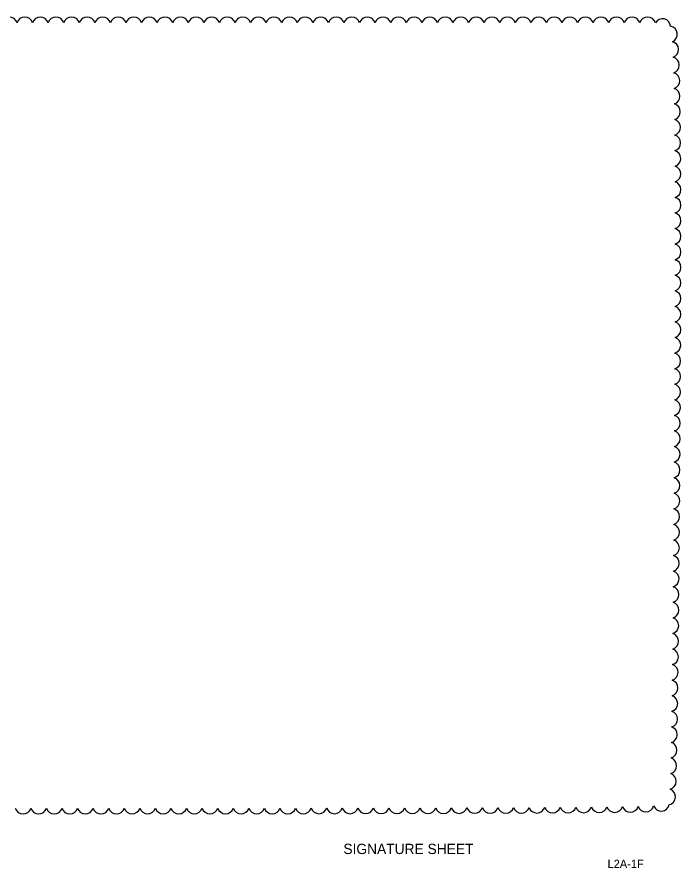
# Model space of a CAD drawing. Extents: x -811 to -790, y -2284 to -2178.
# Drawn here: x -803.16 to -795.1, y -2270.88 to -2260.55 of the extents above; entities that cross this region are included whole.
import ezdxf

# ---------------------------------------------------------------- set-up
doc = ezdxf.new("R2010")
doc.units = 0
for name, color, linetype in [('PlotBorder_dp', 7, 'Continuous'), ('ScratchEle_dp', 7, 'Continuous'), ('SheetLines_dp', 7, 'Continuous')]:
    doc.layers.add(name, color=color, linetype=linetype)

msp = doc.modelspace()

# ---------------------------------------------------------------- linework, layer by layer
at = {"layer": 'ScratchEle_dp'}
for centre, radius, start, end in [((-803.255, -2260.649), 0.0991, 17.5008, 162.5008), ((-803.066, -2260.649), 0.0991, 17.5, 162.5), ((-802.877, -2260.649), 0.0991, 17.5, 162.5), ((-802.688, -2260.649), 0.0991, 17.5, 162.5), ((-802.499, -2260.649), 0.0991, 17.5, 162.5), ((-802.31, -2260.649), 0.0991, 17.5, 162.5), ((-802.121, -2260.649), 0.0991, 17.5, 162.5), ((-801.932, -2260.649), 0.0991, 17.5, 162.5), ((-801.743, -2260.649), 0.0991, 17.5, 162.5), ((-801.554, -2260.649), 0.0991, 17.5, 162.5), ((-801.365, -2260.649), 0.0991, 17.5, 162.5), ((-801.176, -2260.649), 0.0991, 17.5, 162.5), ((-800.987, -2260.649), 0.0991, 17.5, 162.5), ((-800.798, -2260.649), 0.0991, 17.5, 162.5), ((-800.609, -2260.649), 0.0991, 17.5, 162.5), ((-800.42, -2260.649), 0.0991, 17.5, 162.5), ((-800.231, -2260.649), 0.0991, 17.5, 162.5), ((-800.042, -2260.649), 0.0991, 17.5, 162.5), ((-799.853, -2260.649), 0.0991, 17.5, 162.5), ((-799.664, -2260.649), 0.0991, 17.5, 162.5), ((-799.475, -2260.649), 0.0991, 17.5, 162.5), ((-799.286, -2260.649), 0.0991, 17.5, 162.5), ((-799.097, -2260.649), 0.0991, 17.5, 162.5), ((-798.908, -2260.649), 0.0991, 17.5, 162.5), ((-798.719, -2260.649), 0.0991, 17.5, 162.5), ((-798.53, -2260.649), 0.0991, 17.5, 162.5), ((-798.341, -2260.649), 0.0991, 17.5, 162.5), ((-798.152, -2260.649), 0.0991, 17.5, 162.5), ((-797.963, -2260.649), 0.0991, 17.5, 162.5), ((-797.774, -2260.649), 0.0991, 17.5, 162.5), ((-797.585, -2260.649), 0.0991, 17.5, 162.5), ((-797.396, -2260.649), 0.0991, 17.5, 162.5), ((-797.207, -2260.649), 0.0991, 17.5, 162.5), ((-797.018, -2260.649), 0.0991, 17.5, 162.5), ((-796.829, -2260.649), 0.0991, 17.5, 162.5), ((-796.64, -2260.649), 0.0991, 17.5, 162.5), ((-796.451, -2260.649), 0.0991, 17.5, 162.5), ((-796.262, -2260.649), 0.0991, 17.5, 162.5), ((-796.073, -2260.649), 0.0991, 17.5, 162.5), ((-795.884, -2260.649), 0.0991, 17.5, 162.5), ((-795.695, -2260.649), 0.0991, 17.5, 162.5), ((-795.506, -2260.649), 0.0991, 17.5, 162.5), ((-795.326, -2260.669), 0.099, 4.4162, 149.4162), ((-795.245, -2260.759), 0.0992, 294.7802, 79.7802), ((-795.229, -2260.945), 0.0991, 290.3649, 75.3649), ((-795.221, -2261.133), 0.0991, 289.3839, 74.3839), ((-795.215, -2261.322), 0.0991, 288.8712, 73.8712), ((-795.212, -2261.511), 0.0991, 288.5423, 73.5423), ((-795.208, -2261.7), 0.0991, 288.3081, 73.3081), ((-795.206, -2261.889), 0.0991, 288.1304, 73.1304), ((-795.204, -2262.078), 0.0991, 287.9896, 72.9896), ((-795.203, -2262.266), 0.0991, 287.8744, 72.8744), ((-795.202, -2262.455), 0.0991, 287.778, 72.778), ((-795.201, -2262.644), 0.0991, 287.6956, 72.6956), ((-795.2, -2262.833), 0.0991, 287.6243, 72.6243), ((-795.2, -2263.022), 0.0991, 287.5617, 72.5617), ((-795.2, -2263.211), 0.0991, 287.5062, 72.5062), ((-795.2, -2263.4), 0.0991, 287.4565, 72.4565), ((-795.2, -2263.589), 0.0991, 287.4117, 72.4117), ((-795.201, -2263.778), 0.0991, 287.3711, 72.3711), ((-795.201, -2263.967), 0.0991, 287.3339, 72.3339), ((-795.202, -2264.156), 0.0991, 287.2999, 72.2999), ((-795.202, -2264.345), 0.0991, 287.2684, 72.2684), ((-795.203, -2264.534), 0.0991, 287.2394, 72.2394), ((-795.204, -2264.723), 0.0991, 287.2123, 72.2123), ((-795.205, -2264.912), 0.0991, 287.1871, 72.1871), ((-795.206, -2265.101), 0.0991, 287.1635, 72.1635), ((-795.207, -2265.29), 0.0991, 287.1414, 72.1414), ((-795.209, -2265.479), 0.0991, 287.126, 72.126), ((-795.21, -2265.668), 0.0991, 287.1162, 72.1162), ((-795.211, -2265.857), 0.0991, 287.1058, 72.1058), ((-795.212, -2266.046), 0.0991, 287.0946, 72.0946), ((-795.214, -2266.235), 0.0991, 287.0827, 72.0827), ((-795.215, -2266.424), 0.0991, 287.0698, 72.0698), ((-795.217, -2266.613), 0.0991, 287.0559, 72.0559), ((-795.218, -2266.802), 0.0991, 287.0408, 72.0408), ((-795.22, -2266.991), 0.0991, 287.0244, 72.0244), ((-795.221, -2267.18), 0.0991, 287.0064, 72.0064), ((-795.223, -2267.369), 0.0991, 286.9865, 71.9865), ((-795.225, -2267.558), 0.0991, 286.9645, 71.9645), ((-795.226, -2267.747), 0.0991, 286.94, 71.94), ((-795.228, -2267.936), 0.0991, 286.9123, 71.9123), ((-795.23, -2268.125), 0.0991, 286.8807, 71.8807), ((-795.232, -2268.314), 0.0991, 286.8443, 71.8443), ((-795.235, -2268.503), 0.0991, 286.8016, 71.8016), ((-795.237, -2268.692), 0.0991, 286.7507, 71.7507), ((-795.24, -2268.881), 0.0991, 286.6884, 71.6884), ((-795.242, -2269.07), 0.0991, 286.6098, 71.6098), ((-795.246, -2269.259), 0.0991, 286.5063, 71.5063), ((-795.249, -2269.447), 0.0991, 286.3609, 71.3609), ((-795.253, -2269.636), 0.0991, 286.1344, 71.1344), ((-795.258, -2269.825), 0.0991, 285.7012, 70.7012), ((-795.268, -2270.013), 0.099, 283.7418, 68.7418), ((-803.087, -2270.122), 0.0991, 197.4952, 342.4952), ((-802.898, -2270.122), 0.0991, 197.5007, 342.5007), ((-802.709, -2270.122), 0.0991, 197.5043, 342.5043), ((-802.52, -2270.122), 0.0991, 197.5079, 342.5079), ((-802.331, -2270.122), 0.0991, 197.5117, 342.5117), ((-802.142, -2270.122), 0.0991, 197.5156, 342.5156), ((-801.953, -2270.122), 0.0991, 197.5197, 342.5197), ((-801.764, -2270.121), 0.0991, 197.5239, 342.5239), ((-801.575, -2270.121), 0.0991, 197.5284, 342.5284), ((-801.386, -2270.121), 0.0991, 197.533, 342.533), ((-801.197, -2270.121), 0.0991, 197.5379, 342.5379), ((-801.008, -2270.121), 0.0991, 197.543, 342.543), ((-800.819, -2270.121), 0.0991, 197.5483, 342.5483), ((-800.63, -2270.121), 0.0991, 197.554, 342.554), ((-800.441, -2270.121), 0.0991, 197.5599, 342.5599), ((-800.252, -2270.12), 0.0991, 197.5662, 342.5662), ((-800.063, -2270.12), 0.0991, 197.5729, 342.5729), ((-799.874, -2270.12), 0.0991, 197.5799, 342.5799), ((-799.685, -2270.12), 0.0991, 197.5874, 342.5874), ((-799.496, -2270.119), 0.0991, 197.5954, 342.5954), ((-799.307, -2270.119), 0.0991, 197.604, 342.604), ((-799.118, -2270.119), 0.0991, 197.6131, 342.6131), ((-798.929, -2270.118), 0.0991, 197.623, 342.623), ((-798.74, -2270.118), 0.0991, 197.6337, 342.6337), ((-798.551, -2270.117), 0.0991, 197.6452, 342.6452), ((-798.362, -2270.117), 0.0991, 197.6578, 342.6578), ((-798.173, -2270.116), 0.0991, 197.6716, 342.6716), ((-797.984, -2270.116), 0.0991, 197.6868, 342.6868), ((-797.795, -2270.115), 0.0991, 197.7037, 342.7037), ((-797.606, -2270.114), 0.0991, 197.7225, 342.7225), ((-797.417, -2270.114), 0.0991, 197.7438, 342.7438), ((-797.228, -2270.113), 0.0991, 197.768, 342.768), ((-797.039, -2270.112), 0.0991, 197.796, 342.796), ((-796.85, -2270.111), 0.0991, 197.8288, 342.8288), ((-796.661, -2270.11), 0.0991, 197.8681, 342.8681), ((-796.472, -2270.108), 0.0991, 197.9161, 342.9161), ((-796.283, -2270.107), 0.0991, 197.9767, 342.9767), ((-796.094, -2270.105), 0.0991, 198.0568, 343.0568), ((-795.905, -2270.103), 0.0991, 198.1697, 343.1697), ((-795.716, -2270.101), 0.0991, 198.3466, 343.3466), ((-795.528, -2270.097), 0.0991, 198.6898, 343.6898), ((-795.341, -2270.087), 0.0992, 202.4244, 347.4244)]:
    msp.add_arc(centre, radius, start, end, dxfattribs=at)

# ---------------------------------------------------------------- texts
at = {"layer": 'PlotBorder_dp'}
msp.add_text('       SIGNATURE SHEET         ', height=0.125, dxfattribs=at).set_placement((-799.524, -2270.708))
at = {"layer": 'SheetLines_dp'}
msp.add_text('L2A-1F', height=0.1, dxfattribs=at).set_placement((-795.992, -2270.877))

doc.saveas('drawing.dxf')
